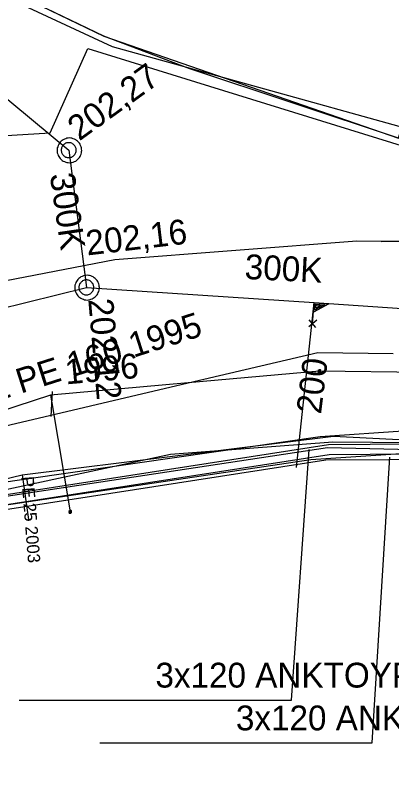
# Model space of a CAD drawing. Extents: x -746464 to -745690, y -1051581 to -1049993.
# Drawn here: x -746426.4 to -746411.28, y -1051044.13 to -1051012.91 of the extents above; entities that cross this region are included whole.
import ezdxf

# ---------------------------------------------------------------- set-up
doc = ezdxf.new("R2010")
doc.units = 0
for name, color, linetype in [('04_CETIN_sdelovaci_podzem', 7, 'Continuous'), ('45_Eltodo_sdelovaci_kabel_ovladaci', 7, 'Continuous'), ('48_Prazs_plynarenska_STL', 7, 'Continuous'), ('48_Prazs_plynarenska_STL_popisy', 7, 'Continuous'), ('51_PVaK_kanal_jednotna_neoverena poloha_pripojka', 7, 'Continuous'), ('51_PVaK_kanal_jednotna_overena poloha_rad', 7, 'Continuous'), ('51_PVaK_kanal_objekty', 7, 'Continuous'), ('51_PVaK_kanal_popisy', 7, 'Continuous'), ('51_PVaK_vodovod_chranicky_objekty', 7, 'Continuous'), ('51_PVaK_vodovod_overena poloha_pripojka', 7, 'Continuous'), ('51_PVaK_vodovod_overena poloha_rad', 7, 'Continuous'), ('51_PVaK_vodovod_popisy', 7, 'Continuous'), ('55_PREdi_NN', 7, 'Continuous'), ('55_PREdi_VN', 7, 'Continuous'), ('55_PREdi_VN_popisy', 7, 'Continuous')]:
    doc.layers.add(name, color=color, linetype=linetype)

msp = doc.modelspace()

# ---------------------------------------------------------------- linework, layer by layer
at = {"layer": '04_CETIN_sdelovaci_podzem'}
for points in [[(-746410.72, -1051017.45), (-746422.5, -1051014.18), (-746428.14, -1051011.55)], [(-746384.52, -1051023.36), (-746404.87, -1051021.93), (-746406.19, -1051021.95), (-746411.69, -1051022), (-746412.67, -1051021.99), (-746422.41, -1051022.74), (-746428.03, -1051023.83), (-746434.88, -1051025.34)], [(-746411.69, -1051022), (-746406.19, -1051021.95)], [(-746426.13, -1051031.39), (-746413.61, -1051029.84), (-746401.2, -1051030.47)], [(-746458.107, -1051041.301), (-746442.74, -1051037.03), (-746439.38, -1051034.68), (-746420.17, -1051030.56), (-746413.63, -1051030.06), (-746402.43, -1051030.16)], [(-746431.74, -1051032.75), (-746426.13, -1051031.39)], [(-746426.13, -1051031.39), (-746425.88, -1051033.19)]]:
    msp.add_lwpolyline(points, dxfattribs=at)
at = {"layer": '45_Eltodo_sdelovaci_kabel_ovladaci'}
msp.add_lwpolyline([(-746458.107, -1051040.596), (-746452.238, -1051038.914), (-746452.533, -1051024.817), (-746441.647, -1051021.908), (-746427.884, -1051017.81), (-746425.007, -1051017.632), (-746423.494, -1051014.247), (-746406.379, -1051019.532), (-746393.969, -1051021.364), (-746377.076, -1051023.037), (-746371.357, -1051023.39), (-746350.592, -1051020.748), (-746343.378, -1051018.106), (-746337.043, -1051014.584), (-746330.796, -1051018.194), (-746332.907, -1051022.157), (-746327.98, -1051025.591), (-746302.693, -1051026.653), (-746280.345, -1051027.533), (-746279.938, -1051027.788)], dxfattribs=at)
at = {"layer": '48_Prazs_plynarenska_STL'}
msp.add_lwpolyline([(-746445.69, -1051035.4), (-746427.32, -1051029.54), (-746419.46, -1051027.69), (-746414.24, -1051026.47), (-746411.209, -1051026.506)], dxfattribs=at)
at = {"layer": '51_PVaK_kanal_jednotna_neoverena poloha_pripojka'}
msp.add_line((-746415.1, -1051031.1), (-746414.385, -1051024.465), dxfattribs=at)
at = {"layer": '51_PVaK_kanal_jednotna_overena poloha_rad'}
for p in [(-746424.26, -1051018.33), (-746442.95, -1051028.64)]:
    msp.add_line(p, (-746423.55, -1051023.85), dxfattribs=at)
for points in [[(-746453.49, -1050994.06), (-746435.493, -1051009.003), (-746424.26, -1051018.33)], [(-746423.55, -1051023.85), (-746414.385, -1051024.465), (-746407.9, -1051024.9)]]:
    msp.add_lwpolyline(points, dxfattribs=at)
at = {"layer": '51_PVaK_kanal_objekty'}
for p, q in [((-746414.284, -1051025.165), (-746414.597, -1051025.441)), ((-746414.312, -1051025.467), (-746414.59, -1051025.149))]:
    msp.add_line(p, q, dxfattribs=at)
for points in [[(-746423.73, -1051018.34), (-746423.74, -1051018.29), (-746423.74, -1051018.24), (-746423.76, -1051018.19), (-746423.78, -1051018.14), (-746423.8, -1051018.09), (-746423.83, -1051018.05), (-746423.86, -1051018.01), (-746423.9, -1051017.97), (-746423.94, -1051017.94), (-746423.98, -1051017.91), (-746424.03, -1051017.89), (-746424.08, -1051017.87), (-746424.13, -1051017.85), (-746424.18, -1051017.85), (-746424.23, -1051017.84), (-746424.28, -1051017.85), (-746424.33, -1051017.85), (-746424.38, -1051017.87), (-746424.43, -1051017.89), (-746424.48, -1051017.91), (-746424.52, -1051017.94), (-746424.56, -1051017.97), (-746424.6, -1051018.01), (-746424.63, -1051018.05), (-746424.66, -1051018.09), (-746424.68, -1051018.14), (-746424.7, -1051018.19), (-746424.72, -1051018.24), (-746424.72, -1051018.29), (-746424.73, -1051018.34), (-746424.72, -1051018.39), (-746424.72, -1051018.44), (-746424.7, -1051018.49), (-746424.68, -1051018.54), (-746424.66, -1051018.59), (-746424.63, -1051018.63), (-746424.6, -1051018.67), (-746424.56, -1051018.71), (-746424.52, -1051018.74), (-746424.48, -1051018.77), (-746424.43, -1051018.79), (-746424.38, -1051018.81), (-746424.33, -1051018.83), (-746424.28, -1051018.83), (-746424.23, -1051018.84), (-746424.18, -1051018.83), (-746424.13, -1051018.83), (-746424.08, -1051018.81), (-746424.03, -1051018.79), (-746423.98, -1051018.77), (-746423.94, -1051018.74), (-746423.9, -1051018.71), (-746423.86, -1051018.67), (-746423.83, -1051018.63), (-746423.8, -1051018.59), (-746423.78, -1051018.54), (-746423.76, -1051018.49), (-746423.74, -1051018.44), (-746423.74, -1051018.39), (-746423.73, -1051018.34)], [(-746423.96, -1051018.33), (-746423.96, -1051018.3), (-746423.966, -1051018.27), (-746423.972, -1051018.24), (-746423.984, -1051018.21), (-746424.002, -1051018.18), (-746424.02, -1051018.156), (-746424.038, -1051018.132), (-746424.062, -1051018.108), (-746424.086, -1051018.09), (-746424.11, -1051018.072), (-746424.14, -1051018.054), (-746424.17, -1051018.042), (-746424.2, -1051018.036), (-746424.23, -1051018.03), (-746424.26, -1051018.03), (-746424.29, -1051018.03), (-746424.32, -1051018.036), (-746424.35, -1051018.042), (-746424.38, -1051018.054), (-746424.41, -1051018.072), (-746424.434, -1051018.09), (-746424.458, -1051018.108), (-746424.482, -1051018.132), (-746424.5, -1051018.156), (-746424.518, -1051018.18), (-746424.536, -1051018.21), (-746424.548, -1051018.24), (-746424.554, -1051018.27), (-746424.56, -1051018.3), (-746424.56, -1051018.33), (-746424.56, -1051018.36), (-746424.554, -1051018.39), (-746424.548, -1051018.42), (-746424.536, -1051018.45), (-746424.518, -1051018.48), (-746424.5, -1051018.504), (-746424.482, -1051018.528), (-746424.458, -1051018.552), (-746424.434, -1051018.57), (-746424.41, -1051018.588), (-746424.38, -1051018.606), (-746424.35, -1051018.618), (-746424.32, -1051018.624), (-746424.29, -1051018.63), (-746424.26, -1051018.63), (-746424.23, -1051018.63), (-746424.2, -1051018.624), (-746424.17, -1051018.618), (-746424.14, -1051018.606), (-746424.11, -1051018.588), (-746424.086, -1051018.57), (-746424.062, -1051018.552), (-746424.038, -1051018.528), (-746424.02, -1051018.504), (-746424.002, -1051018.48), (-746423.984, -1051018.45), (-746423.972, -1051018.42), (-746423.966, -1051018.39), (-746423.96, -1051018.36), (-746423.96, -1051018.33)], [(-746423.02, -1051023.86), (-746423.03, -1051023.81), (-746423.03, -1051023.76), (-746423.05, -1051023.71), (-746423.07, -1051023.66), (-746423.09, -1051023.61), (-746423.12, -1051023.57), (-746423.15, -1051023.53), (-746423.19, -1051023.49), (-746423.23, -1051023.46), (-746423.27, -1051023.43), (-746423.32, -1051023.41), (-746423.37, -1051023.39), (-746423.42, -1051023.37), (-746423.47, -1051023.37), (-746423.52, -1051023.36), (-746423.57, -1051023.37), (-746423.62, -1051023.37), (-746423.67, -1051023.39), (-746423.72, -1051023.41), (-746423.77, -1051023.43), (-746423.81, -1051023.46), (-746423.85, -1051023.49), (-746423.89, -1051023.53), (-746423.92, -1051023.57), (-746423.95, -1051023.61), (-746423.97, -1051023.66), (-746423.99, -1051023.71), (-746424.01, -1051023.76), (-746424.01, -1051023.81), (-746424.02, -1051023.86), (-746424.01, -1051023.91), (-746424.01, -1051023.96), (-746423.99, -1051024.01), (-746423.97, -1051024.06), (-746423.95, -1051024.11), (-746423.92, -1051024.15), (-746423.89, -1051024.19), (-746423.85, -1051024.23), (-746423.81, -1051024.26), (-746423.77, -1051024.29), (-746423.72, -1051024.31), (-746423.67, -1051024.33), (-746423.62, -1051024.35), (-746423.57, -1051024.35), (-746423.52, -1051024.36), (-746423.47, -1051024.35), (-746423.42, -1051024.35), (-746423.37, -1051024.33), (-746423.32, -1051024.31), (-746423.27, -1051024.29), (-746423.23, -1051024.26), (-746423.19, -1051024.23), (-746423.15, -1051024.19), (-746423.12, -1051024.15), (-746423.09, -1051024.11), (-746423.07, -1051024.06), (-746423.05, -1051024.01), (-746423.03, -1051023.96), (-746423.03, -1051023.91), (-746423.02, -1051023.86)], [(-746423.25, -1051023.85), (-746423.25, -1051023.82), (-746423.256, -1051023.79), (-746423.262, -1051023.76), (-746423.274, -1051023.73), (-746423.292, -1051023.7), (-746423.31, -1051023.676), (-746423.328, -1051023.652), (-746423.352, -1051023.628), (-746423.376, -1051023.61), (-746423.4, -1051023.592), (-746423.43, -1051023.574), (-746423.46, -1051023.562), (-746423.49, -1051023.556), (-746423.52, -1051023.55), (-746423.55, -1051023.55), (-746423.58, -1051023.55), (-746423.61, -1051023.556), (-746423.64, -1051023.562), (-746423.67, -1051023.574), (-746423.7, -1051023.592), (-746423.724, -1051023.61), (-746423.748, -1051023.628), (-746423.772, -1051023.652), (-746423.79, -1051023.676), (-746423.808, -1051023.7), (-746423.826, -1051023.73), (-746423.838, -1051023.76), (-746423.844, -1051023.79), (-746423.85, -1051023.82), (-746423.85, -1051023.85), (-746423.85, -1051023.88), (-746423.844, -1051023.91), (-746423.838, -1051023.94), (-746423.826, -1051023.97), (-746423.808, -1051024), (-746423.79, -1051024.024), (-746423.772, -1051024.048), (-746423.748, -1051024.072), (-746423.724, -1051024.09), (-746423.7, -1051024.108), (-746423.67, -1051024.126), (-746423.64, -1051024.138), (-746423.61, -1051024.144), (-746423.58, -1051024.15), (-746423.55, -1051024.15), (-746423.52, -1051024.15), (-746423.49, -1051024.144), (-746423.46, -1051024.138), (-746423.43, -1051024.126), (-746423.4, -1051024.108), (-746423.376, -1051024.09), (-746423.352, -1051024.072), (-746423.328, -1051024.048), (-746423.31, -1051024.024), (-746423.292, -1051024), (-746423.274, -1051023.97), (-746423.262, -1051023.94), (-746423.256, -1051023.91), (-746423.25, -1051023.88), (-746423.25, -1051023.85)], [(-746414.447, -1051025.31), (-746414.39, -1051024.467), (-746413.789, -1051024.507), (-746414.416, -1051024.847)], [(-746414.366, -1051024.766), (-746414.35, -1051024.52), (-746413.965, -1051024.546), (-746414.37, -1051024.765)], [(-746414.316, -1051024.68), (-746414.308, -1051024.557), (-746414.11, -1051024.57), (-746414.32, -1051024.68)]]:
    msp.add_lwpolyline(points, dxfattribs=at)
at = {"layer": '51_PVaK_vodovod_chranicky_objekty'}
for p, q in [((-746414.223, -1051027.174), (-746414.203, -1051027.172)), ((-746414.223, -1051027.174), (-746414.115, -1051027.265)), ((-746414.223, -1051027.174), (-746414.221, -1051027.194)), ((-746414.214, -1051027.273), (-746414.124, -1051027.165)), ((-746414.124, -1051027.165), (-746414.144, -1051027.167)), ((-746414.124, -1051027.165), (-746414.122, -1051027.185)), ((-746414.214, -1051027.273), (-746414.216, -1051027.254)), ((-746414.214, -1051027.273), (-746414.194, -1051027.272)), ((-746414.115, -1051027.265), (-746414.135, -1051027.266)), ((-746414.115, -1051027.265), (-746414.117, -1051027.245)), ((-746424.971, -1051029.04), (-746424.914, -1051028.04)), ((-746424.256, -1051032.84), (-746424.236, -1051032.836)), ((-746424.256, -1051032.84), (-746424.141, -1051032.921)), ((-746424.256, -1051032.84), (-746424.253, -1051032.859)), ((-746424.158, -1051032.823), (-746424.24, -1051032.938)), ((-746424.158, -1051032.823), (-746424.177, -1051032.826)), ((-746424.158, -1051032.823), (-746424.154, -1051032.843)), ((-746424.24, -1051032.938), (-746424.243, -1051032.918)), ((-746424.24, -1051032.938), (-746424.22, -1051032.935)), ((-746424.141, -1051032.921), (-746424.161, -1051032.925)), ((-746424.141, -1051032.921), (-746424.144, -1051032.902))]:
    msp.add_line(p, q, dxfattribs=at)
for points in [[(-746414.119, -1051027.215), (-746414.12, -1051027.21), (-746414.121, -1051027.205), (-746414.123, -1051027.2), (-746414.125, -1051027.195), (-746414.128, -1051027.191), (-746414.132, -1051027.187), (-746414.135, -1051027.183), (-746414.139, -1051027.179), (-746414.144, -1051027.177), (-746414.148, -1051027.174), (-746414.153, -1051027.172), (-746414.158, -1051027.17), (-746414.163, -1051027.17), (-746414.168, -1051027.169), (-746414.173, -1051027.169), (-746414.178, -1051027.17), (-746414.183, -1051027.171), (-746414.188, -1051027.173), (-746414.193, -1051027.175), (-746414.198, -1051027.179), (-746414.201, -1051027.182), (-746414.205, -1051027.185), (-746414.209, -1051027.19), (-746414.211, -1051027.194), (-746414.214, -1051027.198), (-746414.217, -1051027.203), (-746414.218, -1051027.209), (-746414.219, -1051027.214), (-746414.219, -1051027.219), (-746414.219, -1051027.224), (-746414.218, -1051027.229), (-746414.217, -1051027.234), (-746414.215, -1051027.238), (-746414.213, -1051027.243), (-746414.21, -1051027.248), (-746414.206, -1051027.252), (-746414.203, -1051027.255), (-746414.199, -1051027.259), (-746414.194, -1051027.262), (-746414.19, -1051027.264), (-746414.185, -1051027.267), (-746414.18, -1051027.268), (-746414.175, -1051027.269), (-746414.17, -1051027.269), (-746414.165, -1051027.269), (-746414.16, -1051027.269), (-746414.155, -1051027.267), (-746414.15, -1051027.266), (-746414.145, -1051027.263), (-746414.14, -1051027.26), (-746414.137, -1051027.256), (-746414.133, -1051027.253), (-746414.129, -1051027.249), (-746414.127, -1051027.245), (-746414.124, -1051027.24), (-746414.121, -1051027.235), (-746414.12, -1051027.23), (-746414.119, -1051027.225), (-746414.119, -1051027.22), (-746414.119, -1051027.215)], [(-746424.19, -1051032.93), (-746424.185, -1051032.929), (-746424.181, -1051032.927), (-746424.176, -1051032.925), (-746424.171, -1051032.923), (-746424.167, -1051032.919), (-746424.163, -1051032.915), (-746424.16, -1051032.912), (-746424.157, -1051032.907), (-746424.154, -1051032.902), (-746424.152, -1051032.898), (-746424.15, -1051032.893), (-746424.149, -1051032.887), (-746424.149, -1051032.882), (-746424.148, -1051032.877), (-746424.149, -1051032.872), (-746424.15, -1051032.867), (-746424.152, -1051032.862), (-746424.154, -1051032.858), (-746424.157, -1051032.853), (-746424.16, -1051032.849), (-746424.164, -1051032.845), (-746424.168, -1051032.842), (-746424.172, -1051032.839), (-746424.177, -1051032.836), (-746424.181, -1051032.834), (-746424.186, -1051032.832), (-746424.192, -1051032.831), (-746424.197, -1051032.831), (-746424.202, -1051032.83), (-746424.207, -1051032.831), (-746424.212, -1051032.832), (-746424.217, -1051032.834), (-746424.221, -1051032.836), (-746424.226, -1051032.838), (-746424.23, -1051032.842), (-746424.234, -1051032.846), (-746424.237, -1051032.85), (-746424.241, -1051032.854), (-746424.243, -1051032.859), (-746424.245, -1051032.863), (-746424.247, -1051032.868), (-746424.248, -1051032.874), (-746424.249, -1051032.879), (-746424.249, -1051032.884), (-746424.248, -1051032.889), (-746424.247, -1051032.894), (-746424.245, -1051032.899), (-746424.243, -1051032.903), (-746424.241, -1051032.908), (-746424.237, -1051032.912), (-746424.233, -1051032.916), (-746424.23, -1051032.919), (-746424.225, -1051032.923), (-746424.22, -1051032.925), (-746424.216, -1051032.927), (-746424.211, -1051032.929), (-746424.205, -1051032.93), (-746424.2, -1051032.931), (-746424.195, -1051032.931), (-746424.19, -1051032.93)]]:
    msp.add_lwpolyline(points, dxfattribs=at)
at = {"layer": '51_PVaK_vodovod_overena poloha_pripojka'}
for p, q in [((-746424.99, -1051028.19), (-746424.94, -1051028.5)), ((-746424.94, -1051028.5), (-746424.2, -1051032.88))]:
    msp.add_line(p, q, dxfattribs=at)
at = {"layer": '51_PVaK_vodovod_overena poloha_rad'}
msp.add_lwpolyline([(-746405.88, -1051027.33), (-746414.17, -1051027.22), (-746419.46, -1051027.69), (-746424.99, -1051028.19), (-746445.89, -1051035.01)], dxfattribs=at)
at = {"layer": '55_PREdi_NN'}
for points in [[(-746428.573, -1051010.988), (-746422.853, -1051013.746), (-746410.997, -1051017.845), (-746410.472, -1051016.082), (-746409.087, -1051009.798), (-746407.756, -1050996.625), (-746408.308, -1050986.107), (-746409.348, -1050986.162)], [(-746410.997, -1051017.845), (-746419.383, -1051015.06), (-746422.853, -1051013.746), (-746428.45, -1051011.047), (-746434.279, -1051008.237), (-746438.969, -1051004.698), (-746442.457, -1051001.544), (-746444.842, -1050999.388), (-746447.6, -1050996.762), (-746449.257, -1050995.632)], [(-746458.107, -1051047.798), (-746457.998, -1051047.783), (-746456.885, -1051048.928), (-746452.722, -1051047.69), (-746440.383, -1051033.636), (-746414.148, -1051029.846), (-746410.616, -1051029.61), (-746396.676, -1051036.62), (-746398.139, -1051055.821), (-746398.332, -1051057.639)], [(-746399.333, -1051057.595), (-746399.133, -1051055.715), (-746397.724, -1051037.224), (-746410.899, -1051030.552), (-746414.525, -1051030.787), (-746438.583, -1051034.365), (-746438.471, -1051035.121)], [(-746454.884, -1051049.468), (-746454.175, -1051049.401), (-746453.54, -1051048.307), (-746452.342, -1051048.242), (-746448.172, -1051043.945), (-746439.796, -1051034.74), (-746438.929, -1051034.66), (-746413.913, -1051030.787), (-746408.864, -1051030.764), (-746405.306, -1051032.615)]]:
    msp.add_lwpolyline(points, dxfattribs=at)
at = {"layer": '55_PREdi_VN'}
for points in [[(-746458.107, -1051037.308), (-746457.572, -1051041.738), (-746446.525, -1051040.868), (-746440.303, -1051034.503), (-746440.014, -1051034.234), (-746413.813, -1051030.168), (-746402.109, -1051030.075), (-746399.106, -1051032.047), (-746398.436, -1051032.674), (-746396.101, -1051039.06), (-746395.882, -1051039.778), (-746397.231, -1051051.998)], [(-746458.107, -1051040.735), (-746458.016, -1051041.677), (-746446.463, -1051041.049), (-746439.847, -1051034.323), (-746436.082, -1051033.651), (-746413.853, -1051030.29), (-746407.61, -1051030.433), (-746402.17, -1051030.334), (-746399.206, -1051032.224), (-746398.587, -1051032.805), (-746396.606, -1051038.847), (-746396.244, -1051039.951), (-746397.448, -1051051.991), (-746397.722, -1051054.73), (-746397.683, -1051055.515), (-746397.64, -1051056.85)], [(-746458.107, -1051040.642), (-746457.923, -1051042.167), (-746446.344, -1051041.255), (-746440.023, -1051034.789), (-746439.831, -1051034.61), (-746413.781, -1051030.568), (-746402.227, -1051030.476), (-746399.354, -1051032.362), (-746398.779, -1051032.901), (-746396.48, -1051039.187), (-746396.289, -1051039.816), (-746396.864, -1051045.025), (-746397.97, -1051054.644), (-746397.923, -1051055.434)]]:
    msp.add_lwpolyline(points, dxfattribs=at)
at = {"layer": '55_PREdi_VN_popisy'}
for points in [[(-746426.251, -1051040.448), (-746415.292, -1051040.448), (-746414.581, -1051030.365)], [(-746423.013, -1051042.17), (-746412.055, -1051042.17), (-746411.341, -1051030.681)]]:
    msp.add_lwpolyline(points, dxfattribs=at)

# ---------------------------------------------------------------- texts
at = {"layer": '48_Prazs_plynarenska_STL_popisy'}
for s, height, rotation, p in [('STL PE 160 1995', 1, 17.6926, (-746428.879, -1051028.988)), ('PE 25 2003', 0.5, 274.4569, (-746426.167, -1051031.467))]:
    msp.add_text(s, height=height, rotation=rotation, dxfattribs=at).set_placement(p)
at = {"layer": '51_PVaK_kanal_popisy'}
for s, rotation, p in [('202,27', 35.9137, (-746423.836, -1051017.983)), ('300K', 278.3287, (-746425.024, -1051019.311)), ('202,16', 6.7763, (-746423.514, -1051022.568)), ('300K', 357.1617, (-746417.198, -1051023.51)), ('202,12', 274.9441, (-746423.474, -1051024.333)), ('200', 82.8474, (-746414.112, -1051028.973))]:
    msp.add_text(s, height=1, rotation=rotation, dxfattribs=at).set_placement(p)
at = {"layer": '51_PVaK_vodovod_popisy'}
msp.add_text('1996', height=1, rotation=5.1652, dxfattribs=at).set_placement((-746424.371, -1051027.755))
at = {"layer": '55_PREdi_VN_popisy'}
for p in [(-746420.771, -1051039.948), (-746417.534, -1051041.67)]:
    msp.add_text('3x120 ANKTOYPVs', height=1, dxfattribs=at).set_placement(p)

doc.saveas('drawing.dxf')
